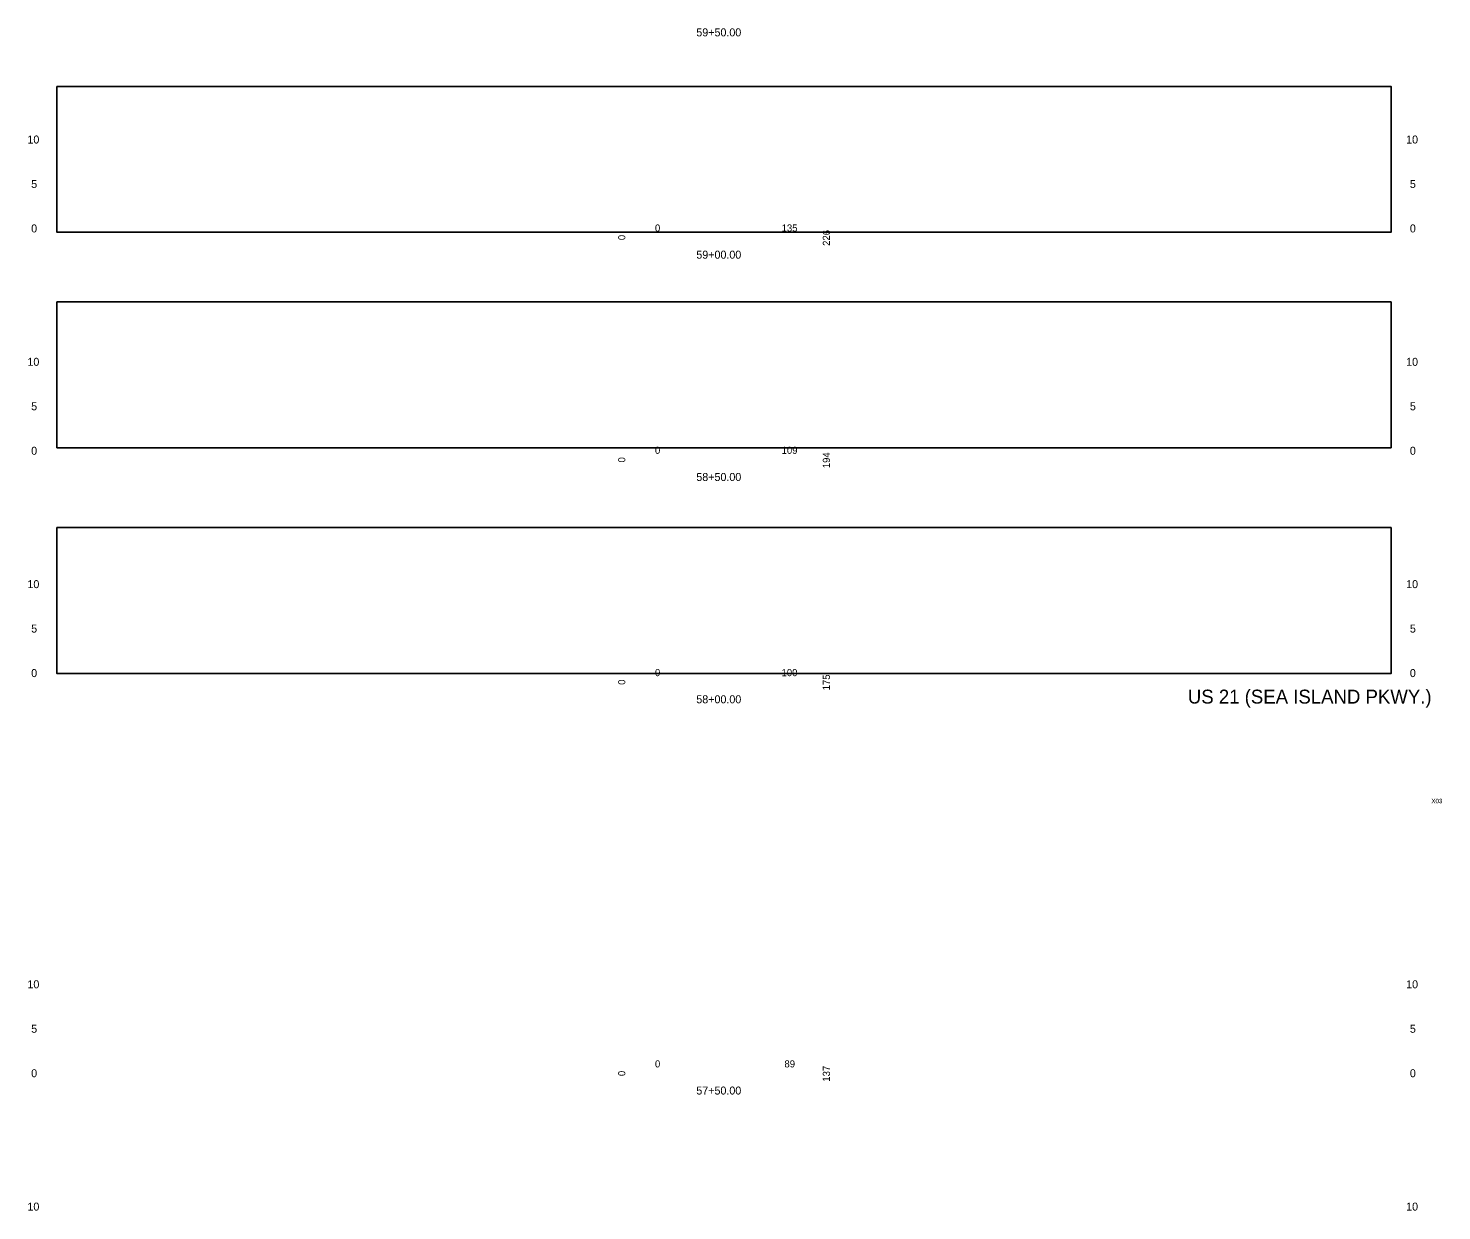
# Model space of a CAD drawing. Extents: x 971 to 1131, y 2203 to 6043.
# Drawn here: x 971.5 to 1130.4, y 2476.9 to 2609.8 of the extents above; entities that cross this region are included whole.
import ezdxf

# ---------------------------------------------------------------- set-up
doc = ezdxf.new("R2010")
doc.units = 0
for name, color, linetype in [('RD_SHT_Misc1', 7, 'Continuous'), ('RD_SHT_ShtClip', 7, 'Continuous'), ('RD_SHT_TX', 7, 'Continuous'), ('RD_XS_TX_Station', 7, 'Continuous')]:
    doc.layers.add(name, color=color, linetype=linetype)

msp = doc.modelspace()

# ---------------------------------------------------------------- linework, layer by layer
at = {"layer": 'RD_SHT_ShtClip'}
for points in [[(974.73, 2603.3), (1124.73, 2603.3), (1124.73, 2586.89), (974.73, 2586.89)], [(974.73, 2579.06), (1124.73, 2579.06), (1124.73, 2562.65), (974.73, 2562.65)], [(974.73, 2553.68), (1124.73, 2553.68), (1124.73, 2537.27), (974.73, 2537.27)]]:
    msp.add_lwpolyline(points, close=True, dxfattribs=at)

# ---------------------------------------------------------------- texts
at = {"layer": 'RD_SHT_Misc1'}
for s, p in [('0', (1041.97, 2586.97)), ('135', (1056.21, 2586.97)), ('0', (1041.97, 2561.97)), ('109', (1056.21, 2561.97)), ('0', (1041.97, 2536.97)), ('100', (1056.2, 2536.97)), ('0', (1041.97, 2492.97)), ('89', (1056.53, 2492.97))]:
    msp.add_text(s, height=0.8, dxfattribs=at).set_placement(p)
for s, p in [('226', (1061.64, 2585.36)), ('0', (1038.63, 2586)), ('194', (1061.64, 2560.36)), ('0', (1038.63, 2561)), ('0', (1038.63, 2536)), ('175', (1061.64, 2535.38)), ('0', (1038.63, 2492)), ('137', (1061.64, 2491.37))]:
    msp.add_text(s, height=0.8, rotation=90, dxfattribs=at).set_placement(p)
at = {"layer": 'RD_SHT_TX'}
for s, height, p in [('10', 0.9, (971.42, 2596.87)), ('10', 0.9, (1126.42, 2596.87)), ('5', 0.9, (971.84, 2591.87)), ('5', 0.9, (1126.84, 2591.87)), ('0', 0.9, (971.84, 2586.87)), ('0', 0.9, (1126.84, 2586.87)), ('10', 0.9, (971.42, 2571.87)), ('10', 0.9, (1126.42, 2571.87)), ('5', 0.9, (971.84, 2566.87)), ('5', 0.9, (1126.84, 2566.87)), ('0', 0.9, (971.84, 2561.87)), ('0', 0.9, (1126.84, 2561.87)), ('10', 0.9, (971.42, 2546.87)), ('10', 0.9, (1126.42, 2546.87)), ('5', 0.9, (971.84, 2541.87)), ('5', 0.9, (1126.84, 2541.87)), ('0', 0.9, (971.84, 2536.87)), ('0', 0.9, (1126.84, 2536.87)), ('US 21 (SEA ISLAND PKWY.)', 1.5625, (1101.88, 2533.89)), ('10', 0.9, (971.42, 2501.87)), ('10', 0.9, (1126.42, 2501.87)), ('5', 0.9, (971.84, 2496.87)), ('5', 0.9, (1126.84, 2496.87)), ('0', 0.9, (971.84, 2491.87)), ('0', 0.9, (1126.84, 2491.87)), ('10', 0.9, (971.42, 2476.87)), ('10', 0.9, (1126.42, 2476.87))]:
    msp.add_text(s, height=height, dxfattribs=at).set_placement(p)
msp.add_text('X03', height=0.5, rotation=360, dxfattribs=at).set_placement((1129.26, 2522.68))
at = {"layer": 'RD_XS_TX_Station'}
for s, p in [('59+50.00', (1046.62, 2608.92)), ('59+00.00', (1046.62, 2583.92)), ('58+50.00', (1046.62, 2558.92)), ('58+00.00', (1046.62, 2533.92)), ('57+50.00', (1046.62, 2489.92))]:
    msp.add_text(s, height=0.9, dxfattribs=at).set_placement(p)

doc.saveas('drawing.dxf')
